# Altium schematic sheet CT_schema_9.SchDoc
size 277 x 170 mm
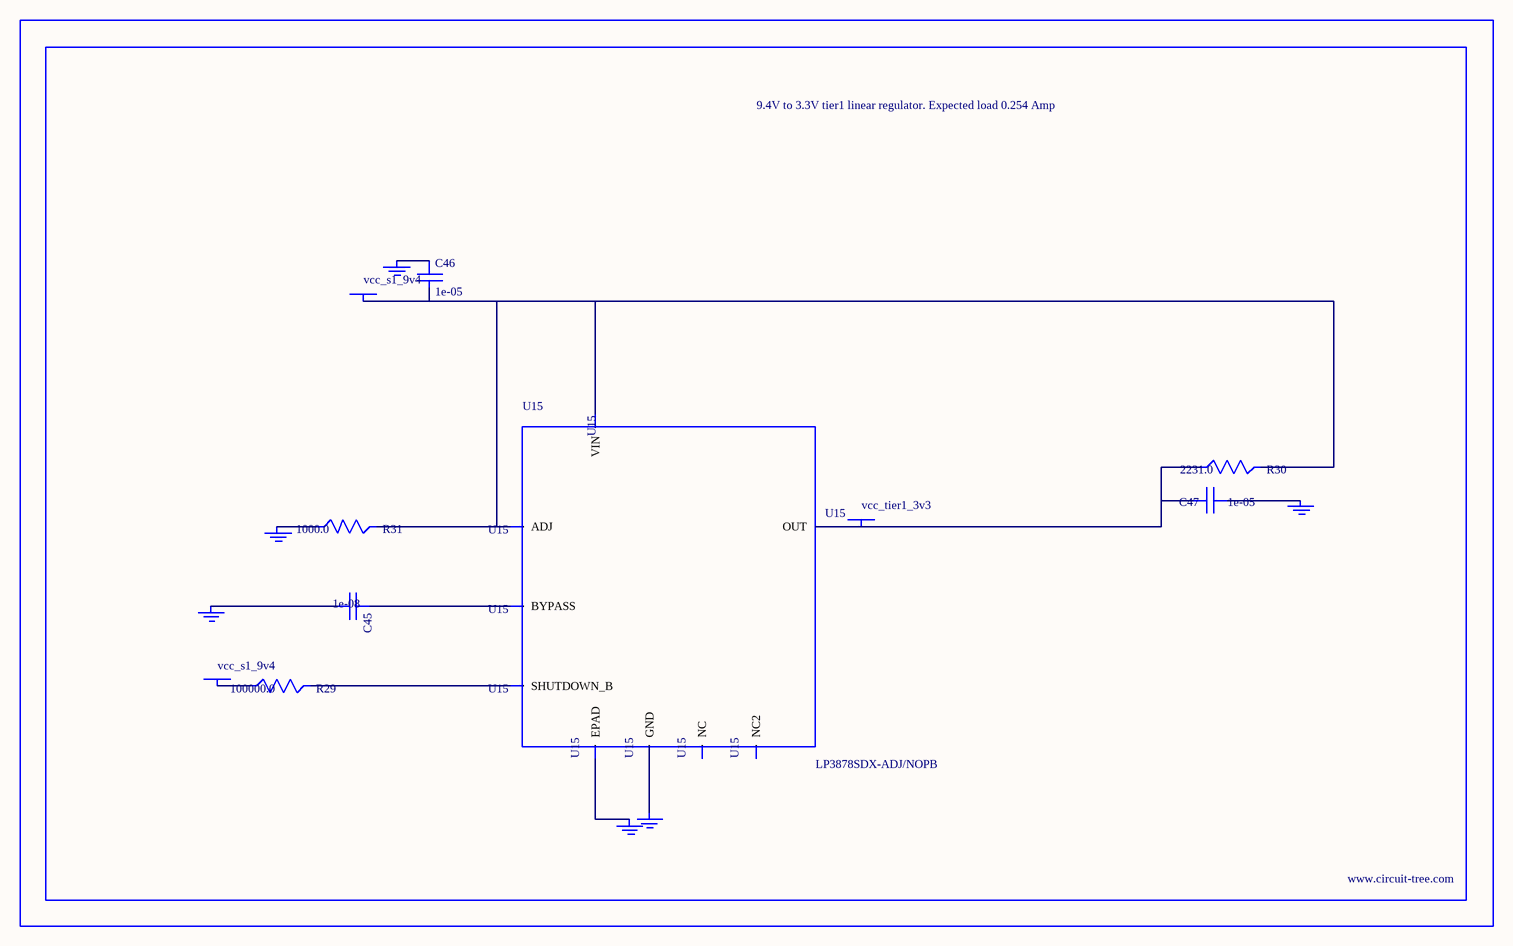
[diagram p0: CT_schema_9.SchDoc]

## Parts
BORDER8  (no value)
C45  1e-08  [C0402]
C46  1e-05  [C1206]
C47  1e-05  [C1210]
GND_INSTANCE_8_0  (no value)
GND_INSTANCE_8_1  (no value)
GND_INSTANCE_8_2  (no value)
GND_INSTANCE_8_3  (no value)
GND_INSTANCE_8_4  (no value)
GND_INSTANCE_8_5  (no value)
POWER_INSTANCE_8_0  vcc_s1_9v4
POWER_INSTANCE_8_1  vcc_s1_9v4
POWER_INSTANCE_8_2  vcc_tier1_3v3
R29  100000.0  [R0603]
R30  2231.0  [R0603]
R31  1000.0  [R0603]
U15  LP3878SDX-ADJ/NOPB  [WSON-8]

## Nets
NetC45_1: C45.1 U15.1(BYPASS)
NetC45_2: C45.2 GND_INSTANCE_8_0.0(GND)
NetC46_1: C46.1 GND_INSTANCE_8_1.0(GND)
NetC46_2: C46.2 POWER_INSTANCE_8_0.0(PWR) R30.2 R31.2 U15.4(VIN) U15.6(ADJ)
NetC47_1: C47.1 GND_INSTANCE_8_2.0(GND)
NetC47_2: C47.2 POWER_INSTANCE_8_2.0(PWR) R30.1 U15.5(OUT)
NetGND_INSTANCE_8_3_0: GND_INSTANCE_8_3.0(GND) R31.1
NetGND_INSTANCE_8_4_0: GND_INSTANCE_8_4.0(GND) U15.PAD(EPAD)
NetGND_INSTANCE_8_5_0: GND_INSTANCE_8_5.0(GND) U15.3(GND)
NetPOWER_INSTANCE_8_1_0: POWER_INSTANCE_8_1.0(PWR) R29.1
NetR29_2: R29.2 U15.8(SHUTDOWN_B)

Not connected (* = marked no-connect by the designer): U15 2(NC) 7(NC2)

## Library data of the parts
BORDER8 = BORDER_PAGE8
C45 = C0402C103K3RAC
C46 = C1206C106K3RACTU
C47 = GRM32DR61E106MA12L
GND_INSTANCE_8_0-GND_INSTANCE_8_5 = GND
POWER_INSTANCE_8_0-POWER_INSTANCE_8_2 = PWR
R29 = RC0603JR-07100KL
R30 = R30
R31 = RC0603JR-071KL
